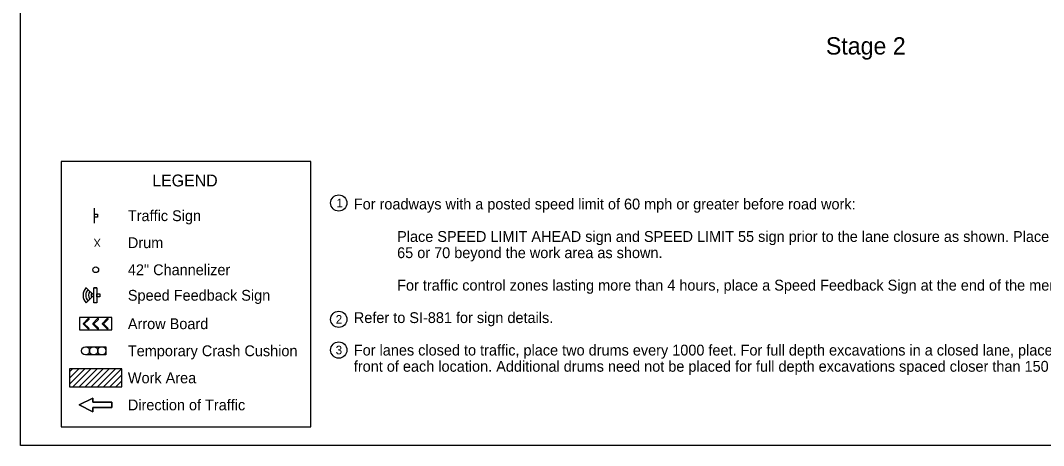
# Model space of a CAD drawing. Extents: x 10133 to 2270741, y 5363 to 1733450.
# Drawn here: x 28133 to 30024, y 7924 to 8710 of the extents above; entities that cross this region are included whole.
import ezdxf

# ---------------------------------------------------------------- set-up
doc = ezdxf.new("R2010")
doc.units = 0
for name, color, linetype in [('dsnNonPlotable', 7, 'Continuous'), ('dsnShtPlotShapeBatchPrint', 7, 'Continuous'), ('dsnStdBlockModified', 7, 'Continuous'), ('dsnStdBorder', 7, 'Continuous'), ('dsnStdDimension', 7, 'Continuous'), ('dsnStdTable', 7, 'Continuous'), ('SheetBorder', 7, 'Continuous')]:
    doc.layers.add(name, color=color, linetype=linetype)

msp = doc.modelspace()

# ---------------------------------------------------------------- linework, layer by layer
at = {"layer": 'dsnNonPlotable'}
msp.add_lwpolyline([(28207.5, 8448.9), (28207.5, 7958.6), (28669.4, 7958.6), (28669.4, 8448.9), (28207.5, 8448.9)], dxfattribs=at)
at = {"layer": 'dsnShtPlotShapeBatchPrint'}
for centre in [(28721, 8372.3), (28721, 8157.2), (28721, 8100.5)]:
    msp.add_circle(centre, 15, dxfattribs=at)
at = {"layer": 'dsnStdBlockModified'}
for p, q in [((28253.9, 8215.8), (28268.1, 8201.7)), ((28273.7, 8215.4), (28268.1, 8215.4)), ((28268.1, 8201.7), (28253.9, 8187.5)), ((28273.7, 8187.9), (28268.1, 8187.9))]:
    msp.add_line(p, q, dxfattribs=at)
for radius, start, end in [(20.3, 135.88, 224.0313), (15.3, 136.1665, 223.7159), (10.3, 136.7294, 223.0963), (5.32, 138.7005, 221.2995)]:
    msp.add_arc((28268.5, 8201.7), radius, start, end, dxfattribs=at)
at = {"layer": 'dsnStdBorder'}
for p, q in [((28269, 8362.5), (28269, 8335)), ((28273.7, 8215.4), (28273.7, 8187.9)), ((28248.8, 8149.8), (28257.7, 8158.7)), ((28266.4, 8149.8), (28275.2, 8158.7)), ((28284, 8149.8), (28292.8, 8158.7)), ((28252.9, 8106.6), (28290.4, 8106.6)), ((28290.4, 8106.6), (28290.4, 8091.6)), ((28290.4, 8091.6), (28252.9, 8091.6)), ((28223.3, 8060.1), (28228.9, 8065.7)), ((28223.3, 8048.8), (28240.3, 8065.7)), ((28223.3, 8037.5), (28251.6, 8065.7)), ((28229.6, 8032.5), (28262.9, 8065.7)), ((28240.9, 8032.5), (28274.2, 8065.7)), ((28252.2, 8032.5), (28285.5, 8065.7)), ((28263.5, 8032.5), (28296.8, 8065.7)), ((28274.9, 8032.5), (28308.1, 8065.7)), ((28286.2, 8032.5), (28319.5, 8065.7)), ((28297.5, 8032.5), (28319.9, 8054.9)), ((28308.8, 8032.5), (28319.9, 8043.6))]:
    msp.add_line(p, q, dxfattribs=at)
for points in [[(28269.1, 8346.1), (28269.1, 8351.7), (28274.7, 8351.7), (28274.7, 8346.1)], [(28268.1, 8187.9), (28268.1, 8215.4), (28273.7, 8215.4), (28273.7, 8187.9)], [(28273.7, 8199), (28273.7, 8204.6), (28279.3, 8204.6), (28279.3, 8199)], [(28301.6, 8160.6), (28241.6, 8160.6), (28241.6, 8137.6), (28301.6, 8137.6)], [(28223.3, 8065.7), (28223.3, 8032.5), (28319.9, 8032.5), (28319.9, 8065.7)], [(28301.3, 8004.1), (28301.3, 7994.1), (28266.3, 7994.1), (28266.3, 7986.6), (28241.3, 7999.1), (28266.3, 8011.6), (28266.3, 8004.1)]]:
    msp.add_lwpolyline(points, close=True, dxfattribs=at)
for points in [[(28259.1, 8157.2), (28259.1, 8157.2), (28250.6, 8149.1), (28259.1, 8141)], [(28276.7, 8157.2), (28276.6, 8157.2), (28268.1, 8149.1), (28276.6, 8141)], [(28294.3, 8157.2), (28294.3, 8157.2), (28285.8, 8149.1), (28294.3, 8141)], [(28257.7, 8139.5), (28257.6, 8139.6), (28248.8, 8148.4), (28248.8, 8148.4)], [(28275.2, 8139.5), (28275.2, 8139.6), (28266.4, 8148.4), (28266.4, 8148.4)], [(28292.9, 8139.5), (28292.8, 8139.6), (28284, 8148.4), (28284, 8148.4)], [(28266.3, 8004.1), (28266.3, 8011.6), (28241.3, 7999.1), (28266.3, 7986.6), (28266.3, 7994.1), (28301.3, 7994.1), (28301.3, 8004.1), (28266.3, 8004.1)]]:
    msp.add_lwpolyline(points, dxfattribs=at)
for centre, radius in [((28271.6, 8248.9), 5.37), ((28271.6, 8248.9), 5.37), ((28252.9, 8099.1), 7.5), ((28252.9, 8099.1), 7.5), ((28267.9, 8099.1), 7.5), ((28267.9, 8099.1), 7.5), ((28282.9, 8099.1), 7.5), ((28282.9, 8099.1), 7.5)]:
    msp.add_circle(centre, radius, dxfattribs=at)
for centre, start, end in [((28258.4, 8157.9), 315.0975, 135.281), ((28275.9, 8157.9), 315.0975, 135.281), ((28293.6, 8157.9), 315.0975, 135.281), ((28249.6, 8149.1), 134.1616, 224.6098), ((28258.4, 8140.3), 226.201, 47.3602), ((28267.1, 8149.1), 134.1616, 224.6098), ((28275.9, 8140.3), 226.201, 47.3602), ((28284.7, 8149.1), 134.1616, 224.6098), ((28293.6, 8140.3), 226.201, 47.3602)]:
    msp.add_arc(centre, 1.03, start, end, dxfattribs=at)
at = {"layer": 'SheetBorder'}
msp.add_lwpolyline([(28132.5, 9944), (31267.5, 9944), (31267.5, 7924), (28132.5, 7924)], close=True, dxfattribs=at)

# ---------------------------------------------------------------- texts
at = {"layer": 'dsnShtPlotShapeBatchPrint'}
for s, p in [('1', (28716.8, 8364.3)), ('2', (28715.4, 8149.2)), ('3', (28715.3, 8092.5))]:
    msp.add_text(s, height=16, dxfattribs=at).set_placement(p)
at = {"layer": 'dsnStdBorder'}
for s, height, p in [('LEGEND', 22, (28376.1, 8402.9)), ('Traffic Sign', 20, (28331.1, 8338.8)), ('Drum', 20, (28331.1, 8288.9)), ('42" Channelizer ', 20, (28331.1, 8238.9)), ('Speed Feedback Sign', 20, (28331.1, 8191.7)), ('Arrow Board', 20, (28331.1, 8139.1)), ('Temporary Crash Cushion', 20, (28331.1, 8089.1)), ('Work Area', 20, (28331.1, 8039.1)), ('Direction of Traffic', 20, (28331.1, 7989.1))]:
    msp.add_text(s, height=height, dxfattribs=at).set_placement(p)
msp.add_text('X', height=15, rotation=180, dxfattribs=at).set_placement((28281.1, 8306.4))
at = {"layer": 'dsnStdDimension'}
msp.add_text('Stage 2', height=32, dxfattribs=at).set_placement((29621.6, 8646.7))
at = {"layer": 'dsnStdTable'}
for s, p in [('For roadways with a posted speed limit of 60 mph or greater before road work:', (28748.9, 8360.4)), ('Place SPEED LIMIT AHEAD sign and SPEED LIMIT 55 sign prior to the lane closure as shown. Place SPEED LIMIT', (28828.9, 8300.4)), ('65 or 70 beyond the work area as shown.', (28828.9, 8270.4)), ('For traffic control zones lasting more than 4 hours, place a Speed Feedback Sign at the end of the merge taper.', (28828.9, 8210.4)), ('Refer to SI-881 for sign details.', (28748.9, 8150.4)), ('For lanes closed to traffic, place two drums every 1000 feet. For full depth excavations in a closed lane, place two drums in ', (28748.9, 8090.4)), ('front of each location. Additional drums need not be placed for full depth excavations spaced closer than 150 feet.', (28748.9, 8060.4))]:
    msp.add_text(s, height=20, dxfattribs=at).set_placement(p)

doc.saveas('drawing.dxf')
